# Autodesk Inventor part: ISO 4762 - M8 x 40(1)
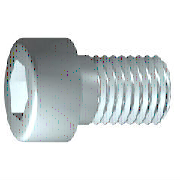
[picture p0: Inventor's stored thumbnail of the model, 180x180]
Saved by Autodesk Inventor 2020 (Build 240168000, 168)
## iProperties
Created: 2019-01
Part Number: ISO 4762 - M8 x 40(1)
Material: Nerezová ocel 440C
Description: Šroub s válcovou hlavou s vnitřním šestihranem
Document SubType Name: Modeling
Standard: ISO 4762
Designer: doma
Standard Revision: Fourth edition 2004-03-01
Standards Organization: ISO
Language: cs-CZ
Size Designation: M8 x 40
Categories: <MemberInstance><Categories><Category DisplayName="Spojovací materiál" InternalName="e4da775c-781d-43d5-af7c-5136215cf5a6" Mnemonic="FSTN"><Category DisplayName
Density: 7.75 g/cm^3
Appearance: Pololeštěná
IsCustomPart: 0
Author: doma
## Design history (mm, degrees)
sketch "Náčrt1"
  geometry: L1 (-2, 0)-(40, 0); L2 (40, 0)-(40, 4); L3 (40, 4)-(12, 4); L4 (12, 4)-(11.233, 4); L5 (11.233, 4)-(0, 4); L6 (0, 4)-(0, 6.5); L7 (0, 6.5)-(-8, 6.5); L8 (-8, 6.5)-(-8, 3.464); L9 (-8, 3.464)-(-4, 3.464); L10 (-4, 3.464)-(-2, 0); L11 (-17.6, 0)-(49.6, 0) reference; L12 (0, -1.3)-(0, 7.8) reference; L13 (12, 4)-(0, 4)
  constraints: 22 end point, 6 parallel, 2 collinear, 2 perpendicular, 1 horizontal, 1 point on line
  dimensions: "d1" = 28 distance from line of L3.end L2 (= GEL); "d2" = 0.76691 distance of L4.end L3.end (computed from GAL); "d3" = 8 distance between parallel lines of L8 L6 (= KOH); "d4" = 4 distance of L8.end L9.end (= INTI); "d5" = 60 deg angle of L10 L1; "d6" = 8 diameter of L3 L1 (= GD); "d7" = 8 diameter of L5 L1 (= BDM); "d8" = 6.9282 diameter of L9 L1 (= 1.1547 x SW); "d9" = 13 diameter of L7 L1 (= KOD); "d26" = 40 distance between parallel lines of L12 L2 (= NLG)
revolve "Těleso" sketch "Náčrt1" stored, may be unused: angle "d10" = 90 deg
sketch "Náčrt2"
  geometry: L1 (0, -9.1)-(0, 9.1) reference; L2 (-9.1, 0)-(9.1, 0) reference; L3 (3.464, 0)-(1.732, -3); L4 (1.732, -3)-(-1.732, -3); L5 (-1.732, -3)-(-3.464, 0); L6 (-3.464, 0)-(-1.732, 3); L7 (-1.732, 3)-(1.732, 3); L8 (1.732, 3)-(3.464, 0); 2 further points
  constraints: 12 end point, 1 coincident, 1 horizontal alignment, 1 point on line, 12 other
extrude "Drážka" join sketch "Náčrt2" stored distance "d11" = 10; taper "d12" = 0 deg
workplane "Work Plane1"
fillet "Fillet2" dims "d30" = 0.1 (= R)
body "Solid1"
fillet "Zaoblení1" dims "d17" = 0.8 (= RR)
feature "Závit" dims "d13" = 28 (= GEL), "d14" = 0
chamfer "Zkosení1" distance "d15" = 0.76681 (= -0.5 x SPD + 0.5 x GD); stored, may be unused: second distance "d16" = 0.76681 (= GUL), angle "d27" = 45 deg
other parameters: "GD" = 8 [user parameter; used in 2 equation terms], "NLG" = 40 [user parameter; used in 1 equation term], "GEL" = 28 [user parameter; used in 2 equation terms], "KOD" = 13 [user parameter; used in 1 equation term], "KOH" = 8 [user parameter; used in 1 equation term], "INTI" = 4 [user parameter; used in 1 equation term], "GAL" = 0.76681 (= 0.61345 x PTC) [user parameter; used in 1 equation term], "GUL" = 0.76681 (= 0.61345 x PTC) [user parameter; used in 1 equation term], "BDM" = 8 (= NND) [user parameter; used in 1 equation term], "SW" = 6 [user parameter; used in 2 equation terms], "RR" = 0.8 [user parameter; used in 1 equation term], "SPD" = 6.46637 (= NND - 1.2269 x PTC) [user parameter; used in 1 equation term], "d19" = 0, "d28" = 0, "d29" = 0, "R" = 0.1 [user parameter; used in 1 equation term], "TOA" = 30 deg [user parameter], "GD1" = 6.46637 (= THREADDIA - 1.2269 x PTC) [user parameter], "THREADDIA" = 8 [user parameter; used in 1 equation term], "FAWI" = 45 deg [user parameter], "TPU" = 8 (computed from PTC) [user parameter], "PTC" = 1.25 [user parameter; used in 5 equation terms], "NND" = 8 [user parameter; used in 2 equation terms], "E0" = 6.93 (= 1.155 x SW) [user parameter]
